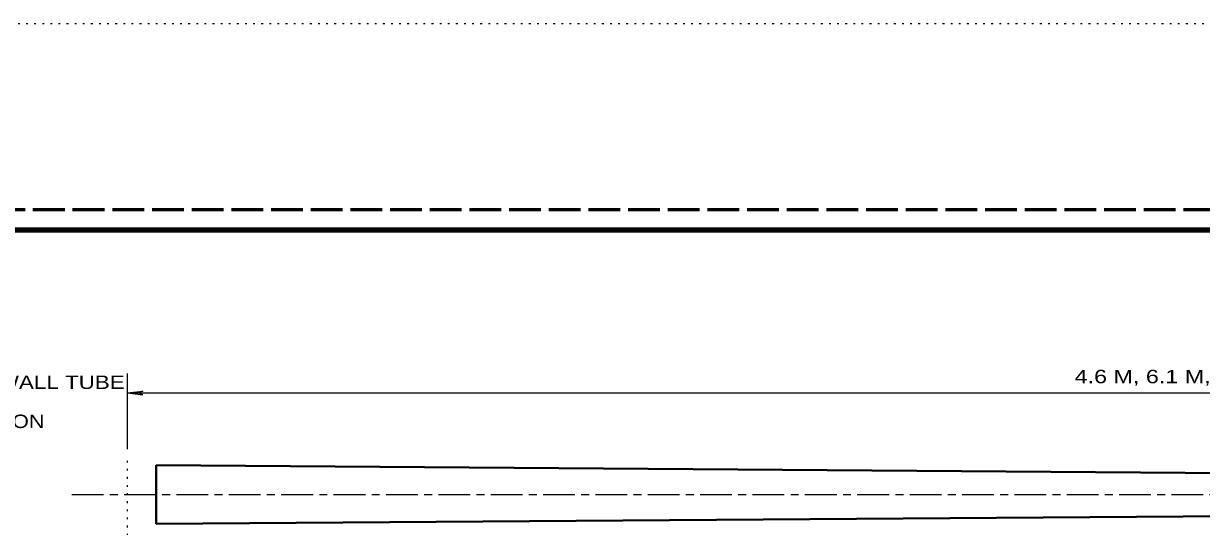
# Model space of a CAD drawing. Extents: x 312583 to 312854, y 144419 to 144597.
# Drawn here: x 312723.4 to 312790.2, y 144568.3 to 144596.8 of the extents above; entities that cross this region are included whole.
import ezdxf

# ---------------------------------------------------------------- set-up
doc = ezdxf.new("R2010")
doc.units = 0
doc.header["$LTSCALE"] = 0.3
for name, pattern in [('DOTTED', [1.5, 0.3, -1.2]), ('LONG_DASH_SHORT_DASH', [9.9, 6, -1.2, 1.5, -1.2]), ('LONG_DASHED', [7.5, 6, -1.5])]:
    doc.linetypes.add(name, pattern=pattern)
for name, color, linetype, lineweight in [('1', 7, 'Continuous', 13), ('62', 7, 'DOTTED', 13), ('63', 7, 'LONG_DASHED', 60)]:
    doc.layers.add(name, color=color, linetype=linetype, lineweight=lineweight)

msp = doc.modelspace()

# ---------------------------------------------------------------- linework, layer by layer
at = {"layer": '1'}
for p, q in [((312729.3174, 144572.6369), (312729.3174, 144576.9258)), ((312729.3174, 144575.826), (312730.1837, 144575.9333)), ((312729.3174, 144575.826), (312844.3174, 144575.826)), ((312729.3174, 144575.826), (312730.1837, 144575.7187)), ((312730.1837, 144575.9333), (312729.9077, 144575.826)), ((312730.1837, 144575.7187), (312729.9077, 144575.826))]:
    msp.add_line(p, q, dxfattribs=at)
at = {"layer": '1', "linetype": 'DOTTED'}
msp.add_line((312729.3174, 144527.7179), (312729.3174, 144572.2382), dxfattribs=at)
at = {"layer": '1', "lineweight": 40}
for p, q in [((312730.935, 144571.7246), (312844.3174, 144570.8966)), ((312730.935, 144568.3972), (312730.935, 144571.7246)), ((312730.935, 144568.3972), (312844.3174, 144569.2252))]:
    msp.add_line(p, q, dxfattribs=at)
at = {"layer": '1', "linetype": 'LONG_DASH_SHORT_DASH'}
msp.add_line((312726.151, 144570.0609), (312847.8219, 144570.0609), dxfattribs=at)
at = {"layer": '1', "lineweight": 158}
msp.add_lwpolyline([(312616.5, 144423.1446), (312616.5, 144585.0846), (312849, 144585.0846)], dxfattribs=at)
at = {"layer": '62'}
msp.add_line((312601.2, 144596.7846), (312853.5, 144596.7846), dxfattribs=at)
at = {"layer": '63'}
msp.add_line((312851.75, 144586.2246), (312583.526, 144586.2246), dxfattribs=at)

# ---------------------------------------------------------------- texts
at = {"layer": '1'}
for s, width, p in [('MIN. 127 MM BY 5 MM WALL TUBE', 1.25, (312708.4015, 144576.0521)), ('4.6 M, 6.1 M, OR 7.6 M', 1.3, (312783.0273, 144576.3771)), ('76 MM BY 165 MM SECTION', 1.2, (312708.4015, 144573.8365))]:
    msp.add_text(s, height=0.76, dxfattribs=dict(at, width=width)).set_placement(p)

doc.saveas('drawing.dxf')
